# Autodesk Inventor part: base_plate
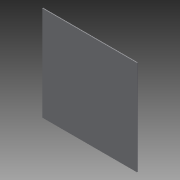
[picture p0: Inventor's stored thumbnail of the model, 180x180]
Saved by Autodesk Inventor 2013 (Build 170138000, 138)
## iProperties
Created: 2008-04
Part Number: base_plate
Document SubType Name: Modeling
Designer: Jayson Martinez
Density: 1 g/cm^3
Material: Generic
Width: 24.000 in
PlateThickness: 0.200 in
Height: 12.000 in
MemberThickness: 0.125 in
MemberWidth: 2.000 in
HorizontalLength: 20.000 in
CornerLength: 12.000 in
SideLength: 8.000 in
Author: Jayson Martinez
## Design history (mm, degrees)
sketch "Sketch1"
  geometry: L1 (0, 0)-(609.6, 0); L2 (609.6, 0)-(609.6, 609.6); L3 (609.6, 609.6)-(0, 609.6); L4 (0, 609.6)-(0, 0)
  constraints: 8 end point, 2 parallel, 1 horizontal, 1 perpendicular
  dimensions: "d3" = 609.6 distance of L1.start L1.end (= Width); "d4" = 609.6 distance of L3.end L1.start (= Width)
extrude "Extrusion1" new body sketch "Sketch1" distance "d0" = 5.08 (= PlateThickness); taper "d1" = 0 deg
sketch "Sketch2"
  geometry: L1 (304.8, 609.6)-(304.8, 0); L2 (609.6, 0)-(0, 0) reference; L3 (0, 609.6)-(609.6, 609.6) reference; C1 r 299.999 at (304.8, 304.8); 1 further point
  constraints: 3 midpoint, 2 end point, 1 centre point, 1 coincident
  dimensions: "d2" = 599.9988 diameter of C1
split "Split1" sketch "Sketch2"
workplane "Work Plane1"
body "Solid1"
other parameters: "Width" = 609.6 [user parameter; used in 4 equation terms], "PlateThickness" = 5.08 [user parameter; used in 1 equation term], "d6" = 304.8 (= 0.5 x Width), "Height" = 304.8 [user parameter; used in 2 equation terms], "MemberThickness" = 3.175 [user parameter], "MemberWidth" = 50.8 [user parameter; used in 2 equation terms], "HorizontalLength" = 508 (= Width - 2 x MemberWidth) [user parameter], "CornerLength" = 304.8 (= Height) [user parameter], "SideLength" = 203.2 (= Height - 2 x MemberWidth) [user parameter]
